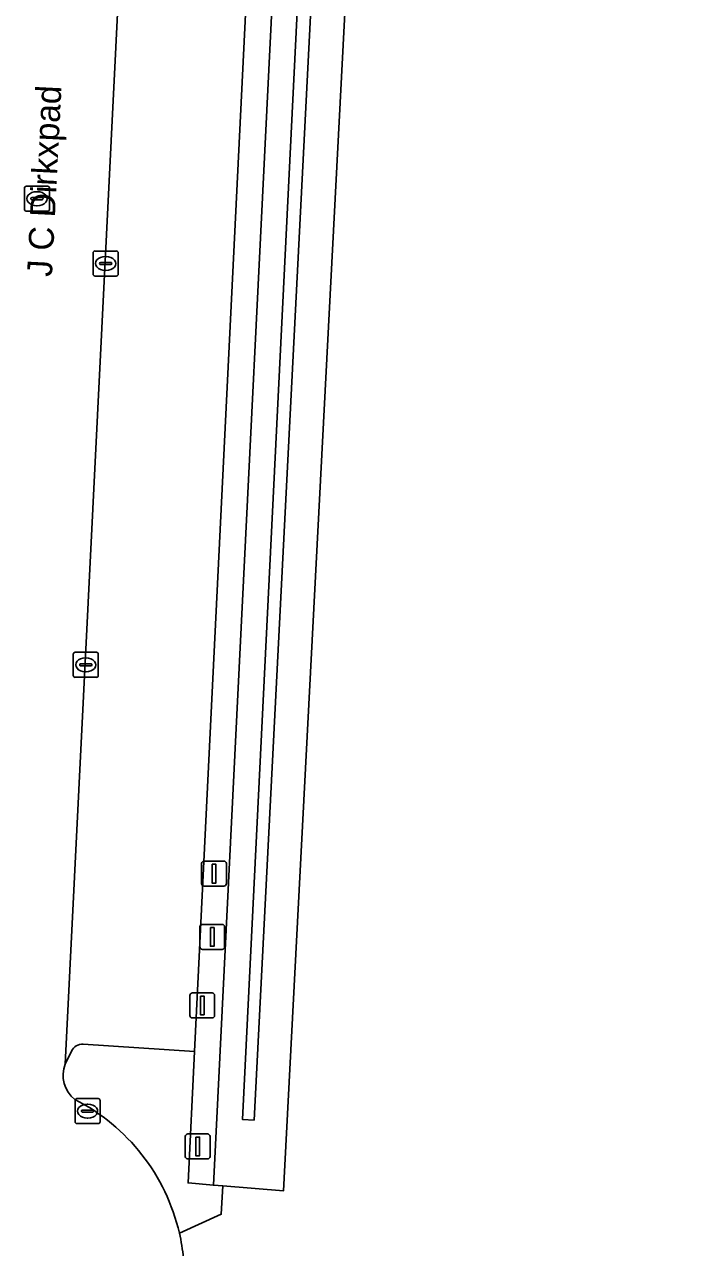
# Model space of a CAD drawing. Extents: x 161758 to 162722, y 384793 to 385405.
# Drawn here: x 162400.23 to 162426.3, y 385116.87 to 385165.8 of the extents above; entities that cross this region are included whole.
import ezdxf

# ---------------------------------------------------------------- set-up
doc = ezdxf.new("R2010")
doc.units = 0
for name, color, linetype in [('IMGEO_Groenvoorziening', 7, 'Continuous'), ('IMGEO_Haag', 7, 'Continuous'), ('IMGEO_Kolk', 7, 'Continuous'), ('IMGEO_Lichtmast', 7, 'Continuous'), ('IMGEO_Loofbos', 7, 'Continuous'), ('IMGEO_Oever', 7, 'Continuous'), ('IMGEO_Openbare_ruimte_label', 7, 'Continuous'), ('IMGEO_Parkeervlak_open', 7, 'Continuous'), ('IMGEO_Rijbaan_lokaal_open', 7, 'Continuous'), ('IMGEO_Rioolput', 7, 'Continuous'), ('IMGEO_Verkeersbordpaal', 7, 'Continuous'), ('IMGEO_Waterloop', 7, 'Continuous')]:
    doc.layers.add(name, color=color, linetype=linetype)

msp = doc.modelspace()

# ---------------------------------------------------------------- linework, layer by layer
at = {"layer": 'IMGEO_Groenvoorziening'}
msp.add_lwpolyline([(162406.773, 385119.449), (162407.783, 385119.36), (162414.261, 385250), (162419.401, 385355.707), (162418.351, 385355.761), (162413.183, 385250), (162407.031, 385124.711)], close=True, dxfattribs=at)
for points in [[(162402.106, 385124.722), (162401.858, 385124.206)], [(162406.423, 385117.443), (162408.096, 385118.196), (162408.166, 385119.329), (162407.783, 385119.36), (162406.773, 385119.449), (162407.031, 385124.711), (162402.58, 385124.997)]]:
    msp.add_lwpolyline(points, dxfattribs=at)
for centre, radius, start, end in [((162402.551, 385124.501), 0.497, 86.6378, 153.6041), ((162402.984, 385123.752), 1.214, 158.053, 232.4983), ((162398.597, 385115.633), 8.032, 13.0256, 62.991)]:
    msp.add_arc(centre, radius, start, end, dxfattribs=at)
at = {"layer": 'IMGEO_Haag'}
for points in [[(162402.106, 385124.722), (162401.858, 385124.206)], [(162406.423, 385117.443), (162408.096, 385118.196), (162408.166, 385119.329), (162407.783, 385119.36), (162406.773, 385119.449), (162407.031, 385124.711), (162402.58, 385124.997)]]:
    msp.add_lwpolyline(points, dxfattribs=at)
for centre, radius, start, end in [((162402.551, 385124.501), 0.497, 86.6378, 153.6041), ((162402.984, 385123.752), 1.214, 158.053, 232.4983), ((162398.597, 385115.633), 8.032, 13.0256, 62.991)]:
    msp.add_arc(centre, radius, start, end, dxfattribs=at)
at = {"layer": 'IMGEO_Kolk'}
for p, q in [((162402.974, 385155.807), (162402.974, 385156.659)), ((162403.049, 385156.733), (162403.901, 385156.733)), ((162403.462, 385156.513), (162403.487, 385156.513)), ((162403.975, 385156.659), (162403.975, 385155.807)), ((162403.233, 385156.227), (162403.233, 385156.239)), ((162403.671, 385156.19), (162403.273, 385156.19)), ((162403.276, 385156.276), (162403.674, 385156.276)), ((162403.485, 385155.953), (162403.46, 385155.953)), ((162403.717, 385156.239), (162403.717, 385156.227)), ((162403.901, 385155.733), (162403.049, 385155.733)), ((162402.179, 385139.752), (162402.179, 385140.604)), ((162402.254, 385140.678), (162403.106, 385140.678)), ((162402.667, 385140.458), (162402.692, 385140.458)), ((162403.18, 385140.604), (162403.18, 385139.752)), ((162402.438, 385140.172), (162402.438, 385140.184)), ((162402.876, 385140.135), (162402.478, 385140.135)), ((162402.481, 385140.221), (162402.879, 385140.221)), ((162402.69, 385139.898), (162402.665, 385139.898)), ((162402.922, 385140.184), (162402.922, 385140.172)), ((162403.106, 385139.678), (162402.254, 385139.678)), ((162402.253, 385121.898), (162402.253, 385122.75)), ((162402.328, 385122.824), (162403.18, 385122.824)), ((162403.254, 385122.75), (162403.254, 385121.898)), ((162402.512, 385122.318), (162402.512, 385122.33)), ((162402.95, 385122.281), (162402.552, 385122.281)), ((162402.555, 385122.367), (162402.953, 385122.367)), ((162402.741, 385122.604), (162402.766, 385122.604)), ((162402.996, 385122.33), (162402.996, 385122.318)), ((162403.18, 385121.824), (162402.328, 385121.824)), ((162402.764, 385122.044), (162402.739, 385122.044))]:
    msp.add_line(p, q, dxfattribs=at)
for points in [[(162402.974, 385155.807), (162402.974, 385156.659)], [(162403.049, 385156.733), (162403.901, 385156.733)], [(162403.975, 385156.659), (162403.975, 385155.807)], [(162403.901, 385155.733), (162403.049, 385155.733)], [(162402.179, 385139.752), (162402.179, 385140.604)], [(162402.254, 385140.678), (162403.106, 385140.678)], [(162403.18, 385140.604), (162403.18, 385139.752)], [(162403.106, 385139.678), (162402.254, 385139.678)], [(162402.253, 385121.898), (162402.253, 385122.75)], [(162402.328, 385122.824), (162403.18, 385122.824)], [(162403.254, 385122.75), (162403.254, 385121.898)], [(162403.18, 385121.824), (162402.328, 385121.824)]]:
    msp.add_lwpolyline(points, dxfattribs=at)
for centre, radius, start, end in [((162403.051, 385156.657), 0.0765, 91.552, 178.448), ((162403.051, 385156.657), 0.0765, 91.552, 178.448), ((162403.899, 385156.657), 0.0765, 1.552, 88.448), ((162403.899, 385156.657), 0.0765, 1.552, 88.448), ((162403.273, 385156.236), 0.0403, 85.8775, 175.7526), ((162403.27, 385156.226), 0.0366, 178.938, 274.7102), ((162403.674, 385156.233), 0.043, 264.8664, 352.4533), ((162403.678, 385156.238), 0.0386, 1.7309, 96.639), ((162403.051, 385155.809), 0.0765, 181.552, 268.448), ((162403.051, 385155.809), 0.0765, 181.552, 268.448), ((162403.899, 385155.809), 0.0765, 271.552, 358.448), ((162403.899, 385155.809), 0.0765, 271.552, 358.448), ((162402.256, 385140.602), 0.0765, 91.552, 178.448), ((162402.256, 385140.602), 0.0765, 91.552, 178.448), ((162403.104, 385140.602), 0.0765, 1.552, 88.448), ((162403.104, 385140.602), 0.0765, 1.552, 88.448), ((162402.478, 385140.181), 0.0403, 85.8775, 175.7526), ((162402.475, 385140.171), 0.0366, 178.938, 274.7102), ((162402.879, 385140.178), 0.043, 264.8664, 352.4533), ((162402.883, 385140.183), 0.0386, 1.7309, 96.639), ((162402.256, 385139.754), 0.0765, 181.552, 268.448), ((162402.256, 385139.754), 0.0765, 181.552, 268.448), ((162403.104, 385139.754), 0.0765, 271.552, 358.448), ((162403.104, 385139.754), 0.0765, 271.552, 358.448), ((162402.33, 385122.748), 0.0765, 91.552, 178.448), ((162402.33, 385122.748), 0.0765, 91.552, 178.448), ((162403.178, 385122.748), 0.0765, 1.552, 88.448), ((162403.178, 385122.748), 0.0765, 1.552, 88.448), ((162402.552, 385122.327), 0.0403, 85.8775, 175.7526), ((162402.549, 385122.317), 0.0366, 178.938, 274.7102), ((162402.953, 385122.324), 0.043, 264.8664, 352.4533), ((162402.957, 385122.329), 0.0386, 1.7309, 96.639), ((162402.33, 385121.9), 0.0765, 181.552, 268.448), ((162402.33, 385121.9), 0.0765, 181.552, 268.448), ((162403.178, 385121.9), 0.0765, 271.552, 358.448), ((162403.178, 385121.9), 0.0765, 271.552, 358.448)]:
    msp.add_arc(centre, radius, start, end, dxfattribs=at)
for centre, major_axis, ratio, start_param, end_param in [((162403.461, 385156.233), (-0.387, 0.002), 0.722429, 4.712389, 7.853982), ((162403.486, 385156.233), (-0.39, 0.002), 0.717154, 1.570796, 4.712389), ((162402.666, 385140.178), (-0.387, 0.002), 0.722429, 4.712389, 7.853982), ((162402.691, 385140.178), (-0.39, 0.002), 0.717154, 1.570796, 4.712389), ((162402.74, 385122.324), (-0.387, 0.002), 0.722429, 4.712389, 7.853982), ((162402.765, 385122.324), (-0.39, 0.002), 0.717154, 1.570796, 4.712389)]:
    msp.add_ellipse(centre, major_axis=major_axis, ratio=ratio, start_param=start_param, end_param=end_param, dxfattribs=at)
at = {"layer": 'IMGEO_Lichtmast'}
for p, q in [((162406.659, 385120.511), (162406.659, 385121.311)), ((162406.659, 385121.311), (162406.659, 385120.511)), ((162406.759, 385121.411), (162407.549, 385121.411)), ((162407.549, 385121.411), (162406.759, 385121.411)), ((162407.649, 385121.311), (162407.649, 385120.511)), ((162407.649, 385120.511), (162407.649, 385121.311)), ((162407.549, 385120.411), (162406.759, 385120.411)), ((162406.759, 385120.411), (162407.549, 385120.411))]:
    msp.add_line(p, q, dxfattribs=at)
msp.add_lwpolyline([(162407.079, 385121.286), (162407.229, 385121.286), (162407.229, 385120.536), (162407.079, 385120.536), (162407.079, 385121.286)], dxfattribs=at)
for centre, start, end in [((162406.759, 385121.311), 90, 180), ((162406.759, 385121.311), 90, 180), ((162407.549, 385121.311), 0, 90), ((162407.549, 385121.311), 360, 90), ((162406.759, 385120.511), 180, 270), ((162406.759, 385120.511), 180, 270), ((162407.549, 385120.511), 270, 0), ((162407.549, 385120.511), 270, 0)]:
    msp.add_arc(centre, 0.1, start, end, dxfattribs=at)
at = {"layer": 'IMGEO_Loofbos'}
msp.add_lwpolyline([(162465.138, 385194.897), (162467.713, 385212.412), (162470.01, 385237.543), (162469.866, 385258.533), (162470.681, 385264.612), (162472.237, 385270.692), (162476.278, 385280.29), (162478.409, 385287.088), (162477.196, 385287.088), (162434.994, 385289.014), (162419.486, 385290.14), (162417.396, 385250), (162410.582, 385119.132), (162408.166, 385119.329), (162408.096, 385118.196), (162406.423, 385117.443)], dxfattribs=at)
msp.add_arc((162398.46, 385115.615), 8.17, 5.8261, 12.9311, dxfattribs=at)
at = {"layer": 'IMGEO_Oever'}
for points in [[(162419.635, 385294.602), (162421.908, 385355.651), (162421.923, 385356.054), (162419.422, 385356.137), (162419.401, 385355.707), (162414.261, 385250), (162407.783, 385119.36), (162408.166, 385119.329), (162410.582, 385119.132), (162417.396, 385250), (162419.486, 385290.14), (162434.994, 385289.014), (162477.196, 385287.088), (162478.245, 385291.84), (162436.99, 385293.977)], [(162418.132, 385293.078), (162476.312, 385290.198), (162475.895, 385288.42), (162418.045, 385291.37), (162409.407, 385121.965), (162408.945, 385121.989), (162420.33, 385352.734), (162421.172, 385352.691)]]:
    msp.add_lwpolyline(points, close=True, dxfattribs=at)
at = {"layer": 'IMGEO_Parkeervlak_open'}
for points in [[(162413.519, 385357.905), (162408.073, 385250), (162405.723, 385201.838), (162401.858, 385124.206), (162402.106, 385124.722)], [(162402.58, 385124.997), (162407.031, 385124.711), (162413.183, 385250), (162418.351, 385355.761), (162415.075, 385355.949)]]:
    msp.add_lwpolyline(points, dxfattribs=at)
msp.add_arc((162402.551, 385124.501), 0.497, 86.6378, 153.6041, dxfattribs=at)
at = {"layer": 'IMGEO_Rijbaan_lokaal_open'}
msp.add_lwpolyline([(162401.858, 385124.206), (162405.723, 385201.838), (162408.073, 385250)], dxfattribs=at)
for centre, radius, start, end in [((162402.984, 385123.752), 1.214, 158.053, 232.4983), ((162398.597, 385115.633), 8.032, 13.0256, 62.991), ((162398.46, 385115.615), 8.17, 5.8261, 12.9311)]:
    msp.add_arc(centre, radius, start, end, dxfattribs=at)
at = {"layer": 'IMGEO_Rioolput'}
for p, q in [((162400.228, 385158.4), (162400.228, 385159.252)), ((162400.303, 385159.326), (162401.155, 385159.326)), ((162400.53, 385158.869), (162400.928, 385158.869)), ((162400.716, 385159.106), (162400.741, 385159.106)), ((162401.229, 385159.252), (162401.229, 385158.4)), ((162400.487, 385158.82), (162400.487, 385158.832)), ((162400.925, 385158.783), (162400.527, 385158.783)), ((162400.739, 385158.546), (162400.714, 385158.546)), ((162400.971, 385158.832), (162400.971, 385158.82)), ((162401.155, 385158.326), (162400.303, 385158.326))]:
    msp.add_line(p, q, dxfattribs=at)
for points in [[(162400.228, 385158.4), (162400.228, 385159.252)], [(162400.303, 385159.326), (162401.155, 385159.326)], [(162401.229, 385159.252), (162401.229, 385158.4)], [(162401.155, 385158.326), (162400.303, 385158.326)]]:
    msp.add_lwpolyline(points, dxfattribs=at)
for centre, radius, start, end in [((162400.305, 385159.25), 0.0765, 91.552, 178.448), ((162400.305, 385159.25), 0.0765, 91.552, 178.448), ((162400.527, 385158.829), 0.0403, 85.8775, 175.7526), ((162400.932, 385158.831), 0.0386, 1.7309, 96.639), ((162401.153, 385159.25), 0.0765, 1.552, 88.448), ((162401.153, 385159.25), 0.0765, 1.552, 88.448), ((162400.305, 385158.402), 0.0765, 181.552, 268.448), ((162400.305, 385158.402), 0.0765, 181.552, 268.448), ((162400.524, 385158.819), 0.0366, 178.938, 274.7102), ((162400.928, 385158.826), 0.043, 264.8664, 352.4533), ((162401.153, 385158.402), 0.0765, 271.552, 358.448), ((162401.153, 385158.402), 0.0765, 271.552, 358.448)]:
    msp.add_arc(centre, radius, start, end, dxfattribs=at)
for centre, major_axis, ratio, start_param, end_param in [((162400.715, 385158.826), (-0.387, 0.002), 0.722429, 4.712389, 7.853982), ((162400.74, 385158.826), (-0.39, 0.002), 0.717154, 1.570796, 4.712389)]:
    msp.add_ellipse(centre, major_axis=major_axis, ratio=ratio, start_param=start_param, end_param=end_param, dxfattribs=at)
at = {"layer": 'IMGEO_Verkeersbordpaal'}
for p, q in [((162407.312, 385131.425), (162407.312, 385132.225)), ((162407.312, 385132.225), (162407.312, 385131.425)), ((162407.412, 385132.325), (162408.202, 385132.325)), ((162408.202, 385132.325), (162407.412, 385132.325)), ((162408.302, 385132.225), (162408.302, 385131.425)), ((162408.302, 385131.425), (162408.302, 385132.225)), ((162408.202, 385131.325), (162407.412, 385131.325)), ((162407.412, 385131.325), (162408.202, 385131.325)), ((162407.243, 385128.894), (162407.243, 385129.694)), ((162407.243, 385129.694), (162407.243, 385128.894)), ((162407.343, 385129.794), (162408.133, 385129.794)), ((162408.133, 385129.794), (162407.343, 385129.794)), ((162408.233, 385129.694), (162408.233, 385128.894)), ((162408.233, 385128.894), (162408.233, 385129.694)), ((162408.133, 385128.794), (162407.343, 385128.794)), ((162407.343, 385128.794), (162408.133, 385128.794)), ((162406.943, 385127.052), (162407.733, 385127.052)), ((162407.733, 385127.052), (162406.943, 385127.052)), ((162406.843, 385126.152), (162406.843, 385126.952)), ((162406.843, 385126.952), (162406.843, 385126.152)), ((162407.833, 385126.952), (162407.833, 385126.152)), ((162407.833, 385126.152), (162407.833, 385126.952)), ((162407.733, 385126.052), (162406.943, 385126.052)), ((162406.943, 385126.052), (162407.733, 385126.052))]:
    msp.add_line(p, q, dxfattribs=at)
for points in [[(162407.732, 385132.2), (162407.882, 385132.2), (162407.882, 385131.45), (162407.732, 385131.45), (162407.732, 385132.2)], [(162407.663, 385129.669), (162407.813, 385129.669), (162407.813, 385128.919), (162407.663, 385128.919), (162407.663, 385129.669)], [(162407.263, 385126.927), (162407.413, 385126.927), (162407.413, 385126.177), (162407.263, 385126.177), (162407.263, 385126.927)]]:
    msp.add_lwpolyline(points, dxfattribs=at)
for centre, start, end in [((162407.412, 385132.225), 90, 180), ((162407.412, 385132.225), 90, 180), ((162408.202, 385132.225), 0, 90), ((162408.202, 385132.225), 360, 90), ((162407.412, 385131.425), 180, 270), ((162407.412, 385131.425), 180, 270), ((162408.202, 385131.425), 270, 0), ((162408.202, 385131.425), 270, 0), ((162407.343, 385129.694), 90, 180), ((162407.343, 385129.694), 90, 180), ((162408.133, 385129.694), 0, 90), ((162408.133, 385129.694), 360, 90), ((162407.343, 385128.894), 180, 270), ((162407.343, 385128.894), 180, 270), ((162408.133, 385128.894), 270, 0), ((162408.133, 385128.894), 270, 0), ((162406.943, 385126.952), 90, 180), ((162406.943, 385126.952), 90, 180), ((162407.733, 385126.952), 0, 90), ((162407.733, 385126.952), 360, 90), ((162406.943, 385126.152), 180, 270), ((162406.943, 385126.152), 180, 270), ((162407.733, 385126.152), 270, 0), ((162407.733, 385126.152), 270, 0)]:
    msp.add_arc(centre, 0.1, start, end, dxfattribs=at)
at = {"layer": 'IMGEO_Waterloop'}
msp.add_lwpolyline([(162418.132, 385293.078), (162421.172, 385352.691), (162420.33, 385352.734), (162408.945, 385121.989), (162409.407, 385121.965), (162418.045, 385291.37), (162475.895, 385288.42), (162476.312, 385290.198)], close=True, dxfattribs=at)

# ---------------------------------------------------------------- texts
at = {"layer": 'IMGEO_Openbare_ruimte_label'}
msp.add_text('J C Dirkxpad', height=1, rotation=87.1347, dxfattribs=at).set_placement((162401.326, 385155.689))

doc.saveas('drawing.dxf')
